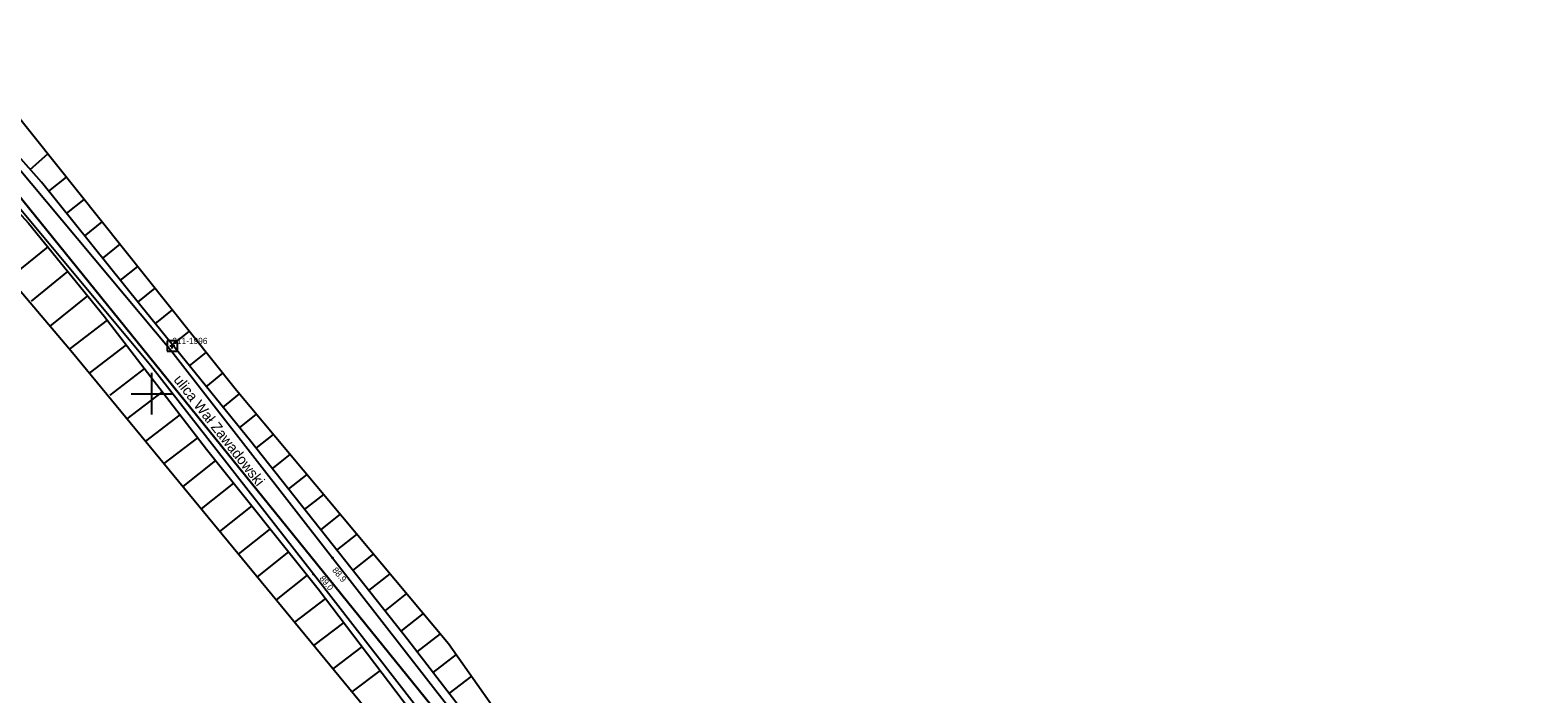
# Model space of a CAD drawing. Extents: x 7506075 to 7506993, y 5784375 to 5786367.
# Drawn here: x 7506285.3 to 7506467.1, y 5786113.8 to 5786193.9 of the extents above; entities that cross this region are included whole.
import ezdxf

# ---------------------------------------------------------------- set-up
doc = ezdxf.new("R2010")
doc.units = 0
for name, color, linetype in [('000 Inne (niezydentyfikowane)', 7, 'Continuous'), ('216-obręb ewidencyjny', 7, 'Continuous'), ('218-kontur użytku gruntowego', 7, 'Continuous'), ('219-działka ewidencyjna', 7, 'Continuous'), ('994-Nazwa ulicy', 7, 'Continuous'), ('jezdnia', 7, 'Continuous'), ('pikieta sztuczna', 7, 'Continuous'), ('pikieta sztuczna-Atr2', 7, 'Continuous'), ('Szczegółowa osnowa geodezyjna pozioma', 7, 'Continuous'), ('Szczegółowa osnowa geodezyjna pozioma-Atr103', 7, 'Continuous'), ('wał przeciwpowodziowy', 7, 'Continuous'), ('Wstawianie ramki sekcyjnej z opisem', 7, 'Continuous')]:
    doc.layers.add(name, color=color, linetype=linetype)

# ---------------------------------------------------------------- blocks, each defined once
blk = doc.blocks.new('PW01')
blk.add_circle((0, 0), 0.045)
blk = doc.blocks.new('OSSP')
for p, q in [((-0.626, 0.625), (-0.626, -0.625)), ((-0.626, 0.625), (-0.626, -0.625)), ((0.624, 0.625), (-0.626, 0.625)), ((0.624, 0.625), (-0.626, 0.625)), ((0.3, 0), (-0.3, 0)), ((0.3, 0), (-0.3, 0)), ((0, -0.3), (0, 0.3)), ((0, -0.3), (0, 0.3)), ((0.624, -0.625), (0.624, 0.625)), ((0.624, -0.625), (0.624, 0.625)), ((-0.626, -0.625), (0.624, -0.625)), ((-0.626, -0.625), (0.624, -0.625))]:
    blk.add_line(p, q)

msp = doc.modelspace()

# ---------------------------------------------------------------- linework, layer by layer
at = {"layer": '000 Inne (niezydentyfikowane)'}
for p, q in [((7506285.33, 5786177.05), (7506287.458, 5786178.933)), ((7506287.56, 5786174.42), (7506289.692, 5786176.133)), ((7506289.72, 5786171.73), (7506291.844, 5786173.434)), ((7506291.89, 5786169.02), (7506294.008, 5786170.721)), ((7506294.05, 5786166.33), (7506296.159, 5786168.024)), ((7506287.43, 5786167.72), (7506282.779, 5786163.949)), ((7506289.84, 5786164.76), (7506285.42, 5786161.18)), ((7506296.18, 5786163.67), (7506298.287, 5786165.356)), ((7506298.29, 5786161.03), (7506300.392, 5786162.717)), ((7506292.23, 5786161.81), (7506287.699, 5786158.14)), ((7506294.59, 5786158.87), (7506290.14, 5786155.44)), ((7506300.39, 5786158.44), (7506302.465, 5786160.117)), ((7506302.47, 5786155.88), (7506304.521, 5786157.54)), ((7506296.88, 5786155.89), (7506292.441, 5786152.473)), ((7506304.53, 5786153.34), (7506306.559, 5786154.985)), ((7506299.09, 5786153.02), (7506294.94, 5786149.83)), ((7506306.56, 5786150.84), (7506308.566, 5786152.468)), ((7506301.24, 5786150.23), (7506296.982, 5786146.957)), ((7506308.57, 5786148.35), (7506310.574, 5786149.973)), ((7506303.37, 5786147.46), (7506299.22, 5786144.27)), ((7506310.57, 5786145.88), (7506312.613, 5786147.538)), ((7506305.49, 5786144.69), (7506301.423, 5786141.564)), ((7506312.56, 5786143.42), (7506314.664, 5786145.089)), ((7506314.51, 5786140.95), (7506316.687, 5786142.673)), ((7506307.65, 5786141.94), (7506303.709, 5786138.787)), ((7506309.83, 5786139.21), (7506305.93, 5786136.089)), ((7506316.47, 5786138.48), (7506318.711, 5786140.255)), ((7506318.42, 5786136.02), (7506320.726, 5786137.848)), ((7506312.03, 5786136.46), (7506308.168, 5786133.37)), ((7506320.36, 5786133.57), (7506322.733, 5786135.453)), ((7506314.25, 5786133.7), (7506310.421, 5786130.635)), ((7506322.3, 5786131.12), (7506324.74, 5786133.055)), ((7506316.48, 5786130.91), (7506312.687, 5786127.881)), ((7506324.23, 5786128.68), (7506326.742, 5786130.665)), ((7506318.72, 5786128.11), (7506314.971, 5786125.108)), ((7506326.17, 5786126.23), (7506328.747, 5786128.27)), ((7506320.95, 5786125.27), (7506317.191, 5786122.411)), ((7506328.11, 5786123.78), (7506330.752, 5786125.875)), ((7506323.14, 5786122.38), (7506319.496, 5786119.611)), ((7506330.05, 5786121.33), (7506332.76, 5786123.476)), ((7506331.98, 5786118.85), (7506334.81, 5786121.028)), ((7506325.34, 5786119.49), (7506321.802, 5786116.81)), ((7506333.91, 5786116.34), (7506336.736, 5786118.511)), ((7506327.52, 5786116.6), (7506324.108, 5786114.01)), ((7506335.85, 5786113.82), (7506338.566, 5786115.91))]:
    msp.add_line(p, q, dxfattribs=at)
at = {"layer": '216-obręb ewidencyjny'}
msp.add_lwpolyline([(7506382.84, 5786051.59), (7506280.83, 5786177.75)], dxfattribs=at)
at = {"layer": '218-kontur użytku gruntowego'}
msp.add_lwpolyline([(7506280.83, 5786177.75), (7506382.84, 5786051.59)], dxfattribs=at)
at = {"layer": '219-działka ewidencyjna'}
for points in [[(7506382.84, 5786051.59), (7506280.83, 5786177.75)], [(7506280.83, 5786177.75), (7506382.84, 5786051.59)]]:
    msp.add_lwpolyline(points, dxfattribs=at)
at = {"layer": 'jezdnia'}
for points in [[(7506281.76, 5786179.81), (7506302.27, 5786155.26), (7506321.78, 5786130.19), (7506341.74, 5786104.53)], [(7506339.3, 5786102.69), (7506319.47, 5786128.21), (7506299.86, 5786153.37), (7506279.54, 5786177.75)]]:
    msp.add_lwpolyline(points, dxfattribs=at)
at = {"layer": 'wał przeciwpowodziowy'}
for points in [[(7506282.93, 5786184.61), (7506310.2, 5786150.42), (7506335.78, 5786119.87), (7506354.86, 5786092.75), (7506376.61, 5786064.79), (7506456.08, 5785962.75), (7506467.13, 5785944.74), (7506463.93, 5785942.79), (7506461.99, 5785946.39), (7506450.74, 5785962.46), (7506437.28, 5785981.06), (7506427.01, 5785994.83), (7506410.32, 5786017.05), (7506395.44, 5786037.18), (7506382.1, 5786054.15), (7506368.4, 5786071.7), (7506356.13, 5786087.44), (7506330.87, 5786120.3), (7506311.93, 5786144.21), (7506298.65, 5786160.59), (7506286.67, 5786175.53), (7506272.19, 5786191.88), (7506274.44, 5786193.87)], [(7506282.93, 5786184.61), (7506310.2, 5786150.42), (7506335.78, 5786119.87), (7506354.86, 5786092.75), (7506376.61, 5786064.79), (7506456.08, 5785962.75), (7506467.13, 5785944.74), (7506463.93, 5785942.79), (7506461.99, 5785946.39), (7506450.74, 5785962.46), (7506437.28, 5785981.06), (7506427.01, 5785994.83), (7506410.32, 5786017.05), (7506395.44, 5786037.18), (7506382.1, 5786054.15), (7506368.4, 5786071.7), (7506356.13, 5786087.44), (7506330.87, 5786120.3), (7506311.93, 5786144.21), (7506298.65, 5786160.59), (7506286.67, 5786175.53), (7506272.19, 5786191.88), (7506274.44, 5786193.87)], [(7506277.25, 5786179.14), (7506285.11, 5786170.59), (7506294.23, 5786159.34), (7506306.57, 5786143.29), (7506320.05, 5786126.45), (7506332.85, 5786109.59), (7506346.03, 5786092.36), (7506359.33, 5786074.75), (7506373.03, 5786057.08), (7506387.5, 5786039.03), (7506400.5, 5786022.04), (7506414.1, 5786003.87), (7506426.46, 5785987.35), (7506439.84, 5785969.65), (7506454.99, 5785948.16), (7506459.49, 5785941.47), (7506453.81, 5785937.94), (7506423.23, 5785985.36), (7506399.39, 5786018.52), (7506372.61, 5786051.08), (7506331.97, 5786104.46), (7506290.41, 5786154.94), (7506264.41, 5786185.63), (7506268.42, 5786189.19)], [(7506277.25, 5786179.14), (7506285.11, 5786170.59), (7506294.23, 5786159.34), (7506306.57, 5786143.29), (7506320.05, 5786126.45), (7506332.85, 5786109.59), (7506346.03, 5786092.36), (7506359.33, 5786074.75), (7506373.03, 5786057.08), (7506387.5, 5786039.03), (7506400.5, 5786022.04), (7506414.1, 5786003.87), (7506426.46, 5785987.35), (7506439.84, 5785969.65), (7506454.99, 5785948.16), (7506459.49, 5785941.47), (7506453.81, 5785937.94), (7506423.23, 5785985.36), (7506399.39, 5786018.52), (7506372.61, 5786051.08), (7506331.97, 5786104.46), (7506290.41, 5786154.94), (7506264.41, 5786185.63), (7506268.42, 5786189.19)]]:
    msp.add_lwpolyline(points, close=True, dxfattribs=at)
at = {"layer": 'Wstawianie ramki sekcyjnej z opisem'}
for points in [[(7506300, 5786147.5), (7506300, 5786152.5)], [(7506297.5, 5786150), (7506302.5, 5786150)]]:
    msp.add_lwpolyline(points, dxfattribs=at)

# ---------------------------------------------------------------- block references
at = {"layer": 'pikieta sztuczna'}
for p in [(7506321.78, 5786130.19), (7506319.47, 5786128.21)]:
    msp.add_blockref('PW01', p, dxfattribs=at)
at = {"layer": 'Szczegółowa osnowa geodezyjna pozioma'}
msp.add_blockref('OSSP', (7506302.46, 5786155.74), dxfattribs=at)

# ---------------------------------------------------------------- texts
at = {"layer": '994-Nazwa ulicy'}
msp.add_text('ulica Wał Zawadowski', height=1.25, rotation=308.199, dxfattribs=at).set_placement((7506302.55, 5786151.65))
at = {"layer": 'pikieta sztuczna-Atr2'}
for s, rotation, p in [('89.0', 310.151, (7506320.142, 5786127.653)), ('88.9', 310.084, (7506321.699, 5786128.663))]:
    msp.add_text(s, height=0.75, rotation=rotation, dxfattribs=at).set_placement(p)
at = {"layer": 'Szczegółowa osnowa geodezyjna pozioma-Atr103'}
msp.add_text('211-1996', height=0.75, dxfattribs=at).set_placement((7506302.46, 5786155.99))

doc.saveas('drawing.dxf')
